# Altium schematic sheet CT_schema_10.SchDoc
size 281 x 153 mm
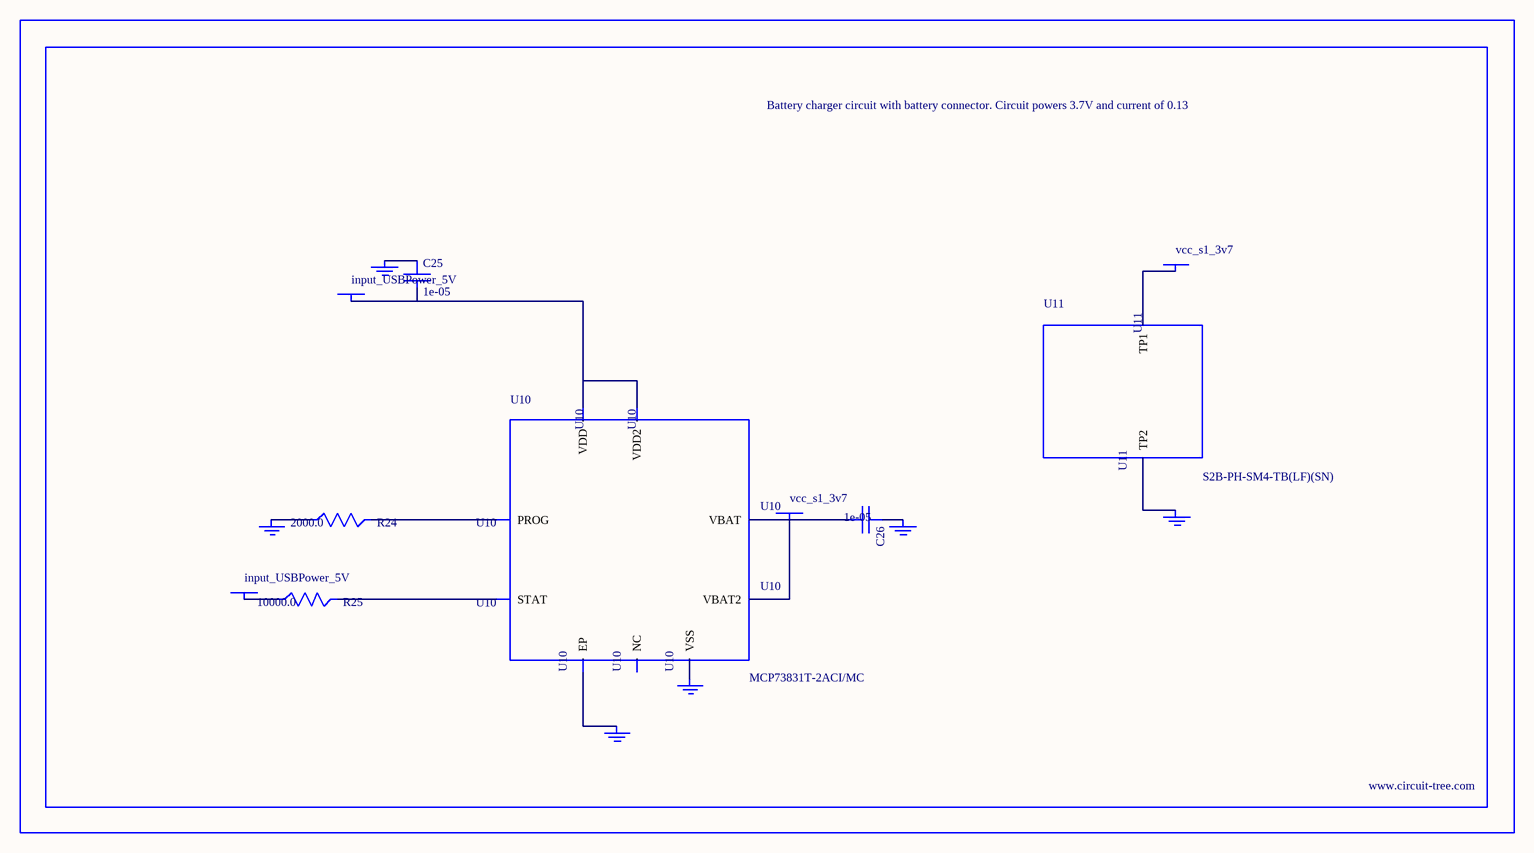
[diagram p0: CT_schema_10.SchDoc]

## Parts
BORDER9  (no value)
C25  1e-05  [C1206]
C26  1e-05  [C1206]
GND_INSTANCE_9_0  (no value)
GND_INSTANCE_9_1  (no value)
GND_INSTANCE_9_2  (no value)
GND_INSTANCE_9_3  (no value)
GND_INSTANCE_9_4  (no value)
GND_INSTANCE_9_5  (no value)
POWER_INSTANCE_9_0  input_USBPower_5V
POWER_INSTANCE_9_1  input_USBPower_5V
POWER_INSTANCE_9_2  vcc_s1_3v7
POWER_INSTANCE_9_3  vcc_s1_3v7
R24  2000.0  [R0603]
R25  10000.0  [R0603]
U10  MCP73831T-2ACI/MC  [DFN8_2X3MC]
U11  S2B-PH-SM4-TB(LF)(SN)  [JST-2-SMD]

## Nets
NetC25_1: C25.1 GND_INSTANCE_9_0.0(GND)
NetC25_2: C25.2 POWER_INSTANCE_9_0.0(PWR) U10.1(VDD) U10.2(VDD2)
NetC26_1: C26.1 GND_INSTANCE_9_1.0(GND)
NetC26_2: C26.2 POWER_INSTANCE_9_2.0(PWR) U10.3(VBAT) U10.4(VBAT2)
NetGND_INSTANCE_9_2_0: GND_INSTANCE_9_2.0(GND) R24.1
NetGND_INSTANCE_9_3_0: GND_INSTANCE_9_3.0(GND) U10.9(EP)
NetGND_INSTANCE_9_4_0: GND_INSTANCE_9_4.0(GND) U10.6(VSS)
NetGND_INSTANCE_9_5_0: GND_INSTANCE_9_5.0(GND) U11.2(TP2)
NetPOWER_INSTANCE_9_1_0: POWER_INSTANCE_9_1.0(PWR) R25.1
NetPOWER_INSTANCE_9_3_0: POWER_INSTANCE_9_3.0(PWR) U11.1(TP1)
NetR24_2: R24.2 U10.8(PROG)
NetR25_2: R25.2 U10.5(STAT)

Not connected (* = marked no-connect by the designer): U10 7(NC)

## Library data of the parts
BORDER9 = BORDER_PAGE9
C25 C26 = C1206C106K3RACTU
GND_INSTANCE_9_0-GND_INSTANCE_9_5 = GND
POWER_INSTANCE_9_0-POWER_INSTANCE_9_3 = PWR
R24 = RC0603JR-072KL
R25 = RC0603JR-0710KL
